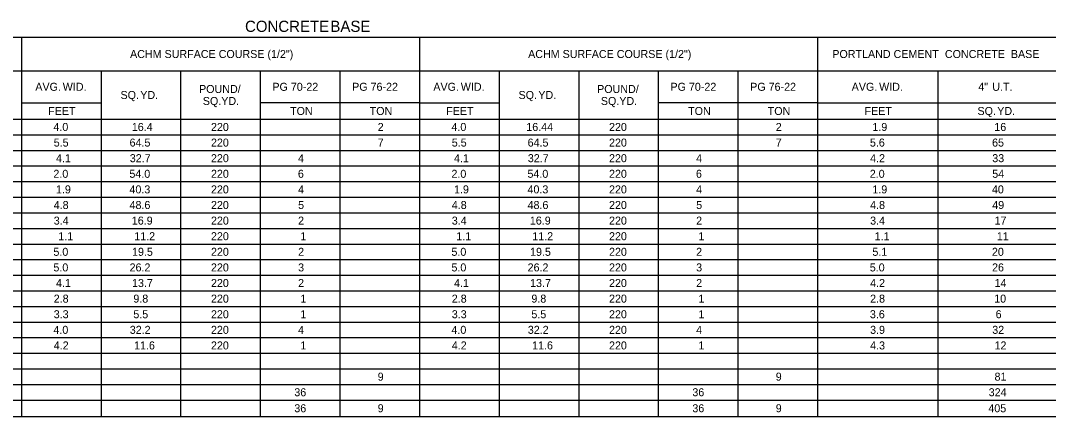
# Model space of a CAD drawing. Extents: x 1226567 to 1228151, y 151309 to 152305.
# Drawn here: x 1227158 to 1227800, y 151364 to 151611 of the extents above; entities that cross this region are included whole.
import ezdxf

# ---------------------------------------------------------------- set-up
doc = ezdxf.new("R2010")
doc.units = 0
doc.layers.add('R_Dimension', color=7, linetype='Continuous')

msp = doc.modelspace()

# ---------------------------------------------------------------- linework, layer by layer
at = {"layer": 'R_Dimension'}
for p, q in [((1226721.38, 151600.64), (1227956.7, 151600.64)), ((1227159.15, 151363.71), (1227159.15, 151600.64)), ((1227407.78, 151363.71), (1227407.78, 151600.64)), ((1227656.4, 151363.71), (1227656.4, 151600.64)), ((1227009.98, 151579.68), (1227956.7, 151579.68)), ((1227208.88, 151363.71), (1227208.88, 151579.68)), ((1227258.6, 151363.71), (1227258.6, 151579.68)), ((1227308.33, 151363.71), (1227308.33, 151579.68)), ((1227308.33, 151559.69), (1227308.33, 151579.68)), ((1227358.05, 151363.71), (1227358.05, 151579.68)), ((1227457.5, 151363.71), (1227457.5, 151579.68)), ((1227507.23, 151363.71), (1227507.23, 151579.68)), ((1227556.95, 151363.71), (1227556.95, 151579.68)), ((1227556.95, 151559.69), (1227556.95, 151579.68)), ((1227606.68, 151363.71), (1227606.68, 151579.68)), ((1227731.48, 151363.71), (1227731.48, 151579.68)), ((1227159.15, 151559.69), (1227208.88, 151559.69)), ((1227407.78, 151559.69), (1227308.33, 151559.69)), ((1227407.78, 151559.69), (1227457.5, 151559.69)), ((1227656.4, 151559.69), (1227556.95, 151559.69)), ((1227656.4, 151559.69), (1227956.7, 151559.69)), ((1226721.38, 151549.45), (1227757.8, 151549.45)), ((1227059.7, 151549.45), (1227208.88, 151549.45)), ((1227208.88, 151549.45), (1227358.05, 151549.45)), ((1227457.5, 151549.45), (1227956.7, 151549.45)), ((1226721.38, 151539.7), (1227956.7, 151539.7)), ((1226721.38, 151529.95), (1227956.7, 151529.95)), ((1226721.38, 151520.2), (1227956.7, 151520.2)), ((1226721.38, 151510.45), (1227956.7, 151510.45)), ((1226721.38, 151500.7), (1227956.7, 151500.7)), ((1226721.38, 151490.95), (1227956.7, 151490.95)), ((1226721.38, 151481.2), (1227956.7, 151481.2)), ((1226721.38, 151471.45), (1227956.7, 151471.45)), ((1226721.38, 151461.7), (1227956.7, 151461.7)), ((1226721.38, 151451.95), (1227956.7, 151451.95)), ((1226721.38, 151442.2), (1227956.7, 151442.2)), ((1226721.38, 151432.45), (1227956.7, 151432.45)), ((1226721.38, 151422.7), (1227956.7, 151422.7)), ((1226721.38, 151412.95), (1227956.7, 151412.95)), ((1226721.38, 151403.2), (1227956.7, 151403.2)), ((1226721.38, 151393.45), (1227956.7, 151393.45)), ((1226721.38, 151383.7), (1227956.7, 151383.7)), ((1226721.38, 151373.95), (1227956.7, 151373.95)), ((1226721.38, 151363.71), (1227956.7, 151363.71))]:
    msp.add_line(p, q, dxfattribs=at)

# ---------------------------------------------------------------- texts
for s, height, p in [('CONCRETE', 7, (1227298.62, 151603.96)), (' BASE', 7, (1227349.33, 151603.96)), ('ACHM SURFACE COURSE (1/2")', 5, (1227226.81, 151587.66)), ('ACHM SURFACE COURSE (1/2")', 5, (1227475.44, 151587.66)), ('PORTLAND', 5, (1227665.44, 151587.66)), (' CEMENT', 5, (1227701.85, 151587.66)), (' CONCRETE', 5, (1227733.9, 151587.66)), (' BASE', 5, (1227775.12, 151587.66)), ('AVG.', 5, (1227167.62, 151567.18)), (' WID.', 5, (1227182.89, 151567.18)), ('POUND/', 5, (1227269.9, 151565.81)), ('PG 70-22', 5, (1227315.71, 151567.18)), ('PG 76-22', 5, (1227365.51, 151567.18)), ('AVG.', 5, (1227416.24, 151567.18)), (' WID.', 5, (1227431.52, 151567.18)), ('POUND/', 5, (1227518.53, 151565.81)), ('PG 70-22', 5, (1227564.34, 151567.18)), ('PG 76-22', 5, (1227614.14, 151567.18)), ('AVG.', 5, (1227677.54, 151567.18)), (' WID.', 5, (1227692.82, 151567.18)), ('4"', 5, (1227756.61, 151567.18)), (' U.T.', 5, (1227763.5, 151567.18)), ('SQ.', 5, (1227220.85, 151562.06)), (' YD.', 5, (1227231.32, 151562.06)), ('SQ.', 5, (1227469.47, 151562.06)), (' YD.', 5, (1227479.95, 151562.06)), ('SQ.YD.', 5, (1227272.25, 151558.31)), ('SQ.YD.', 5, (1227520.87, 151558.31)), ('FEET', 5, (1227175.65, 151552.07)), ('TON', 5, (1227326.75, 151552.07)), ('TON', 5, (1227376.48, 151552.07)), ('FEET', 5, (1227424.28, 151552.07)), ('TON', 5, (1227575.38, 151552.07)), ('TON', 5, (1227625.1, 151552.07)), ('FEET', 5, (1227685.58, 151552.07)), ('SQ.', 5, (1227756.12, 151552.07)), (' YD.', 5, (1227766.6, 151552.07)), ('4.0', 5, (1227178.92, 151542.08)), ('16.4', 5, (1227227.91, 151542.08)), ('220', 5, (1227277.34, 151542.08)), ('2', 5, (1227381.5, 151542.08)), ('4.0', 5, (1227427.54, 151542.08)), ('16.44', 5, (1227474.3, 151542.08)), ('220', 5, (1227525.97, 151542.08)), ('2', 5, (1227630.12, 151542.08)), ('1.9', 5, (1227690.46, 151542.08)), ('16', 5, (1227766.63, 151542.08)), ('5.5', 5, (1227179.13, 151532.33)), ('64.5', 5, (1227226.5, 151532.33)), ('220', 5, (1227277.34, 151532.33)), ('7', 5, (1227381.5, 151532.33)), ('5.5', 5, (1227427.76, 151532.33)), ('64.5', 5, (1227475.12, 151532.33)), ('220', 5, (1227525.97, 151532.33)), ('7', 5, (1227630.12, 151532.33)), ('5.6', 5, (1227688.92, 151532.33)), ('65', 5, (1227765.24, 151532.33)), ('4.1', 5, (1227180.55, 151522.58)), ('32.7', 5, (1227226.62, 151522.58)), ('220', 5, (1227277.34, 151522.58)), ('4', 5, (1227331.77, 151522.58)), ('4.1', 5, (1227429.18, 151522.58)), ('32.7', 5, (1227475.24, 151522.58)), ('220', 5, (1227525.97, 151522.58)), ('4', 5, (1227580.4, 151522.58)), ('4.2', 5, (1227689.06, 151522.58)), ('33', 5, (1227765.35, 151522.58)), ('2.0', 5, (1227178.92, 151512.83)), ('54.0', 5, (1227226.4, 151512.83)), ('220', 5, (1227277.34, 151512.83)), ('6', 5, (1227331.64, 151512.83)), ('2.0', 5, (1227427.54, 151512.83)), ('54.0', 5, (1227475.02, 151512.83)), ('220', 5, (1227525.97, 151512.83)), ('6', 5, (1227580.26, 151512.83)), ('2.0', 5, (1227688.84, 151512.83)), ('54', 5, (1227765.35, 151512.83)), ('1.9', 5, (1227180.53, 151503.08)), ('40.3', 5, (1227226.42, 151503.08)), ('220', 5, (1227277.34, 151503.08)), ('4', 5, (1227331.77, 151503.08)), ('1.9', 5, (1227429.16, 151503.08)), ('40.3', 5, (1227475.04, 151503.08)), ('220', 5, (1227525.97, 151503.08)), ('4', 5, (1227580.4, 151503.08)), ('1.9', 5, (1227690.46, 151503.08)), ('40', 5, (1227765.14, 151503.08)), ('4.8', 5, (1227179.13, 151493.33)), ('48.6', 5, (1227226.48, 151493.33)), ('220', 5, (1227277.34, 151493.33)), ('5', 5, (1227331.77, 151493.33)), ('4.8', 5, (1227427.76, 151493.33)), ('48.6', 5, (1227475.1, 151493.33)), ('220', 5, (1227525.97, 151493.33)), ('5', 5, (1227580.4, 151493.33)), ('4.8', 5, (1227689.06, 151493.33)), ('49', 5, (1227765.34, 151493.33)), ('3.4', 5, (1227179.13, 151483.58)), ('16.9', 5, (1227227.89, 151483.58)), ('220', 5, (1227277.34, 151483.58)), ('2', 5, (1227331.77, 151483.58)), ('3.4', 5, (1227427.76, 151483.58)), ('16.9', 5, (1227476.52, 151483.58)), ('220', 5, (1227525.97, 151483.58)), ('2', 5, (1227580.4, 151483.58)), ('3.4', 5, (1227689.06, 151483.58)), ('17', 5, (1227766.77, 151483.58)), ('1.1', 5, (1227181.97, 151473.83)), ('11.2', 5, (1227229.45, 151473.83)), ('220', 5, (1227277.34, 151473.83)), ('1', 5, (1227333.19, 151473.83)), ('1.1', 5, (1227430.59, 151473.83)), ('11.2', 5, (1227478.07, 151473.83)), ('220', 5, (1227525.97, 151473.83)), ('1', 5, (1227581.82, 151473.83)), ('1.1', 5, (1227691.89, 151473.83)), ('11', 5, (1227768.19, 151473.83)), ('5.0', 5, (1227178.92, 151464.08)), ('19.5', 5, (1227228.03, 151464.08)), ('220', 5, (1227277.34, 151464.08)), ('2', 5, (1227331.77, 151464.08)), ('5.0', 5, (1227427.54, 151464.08)), ('19.5', 5, (1227476.66, 151464.08)), ('220', 5, (1227525.97, 151464.08)), ('2', 5, (1227580.4, 151464.08)), ('5.1', 5, (1227690.48, 151464.08)), ('20', 5, (1227765.14, 151464.08)), ('5.0', 5, (1227178.92, 151454.33)), ('26.2', 5, (1227226.5, 151454.33)), ('220', 5, (1227277.34, 151454.33)), ('3', 5, (1227331.77, 151454.33)), ('5.0', 5, (1227427.54, 151454.33)), ('26.2', 5, (1227475.12, 151454.33)), ('220', 5, (1227525.97, 151454.33)), ('3', 5, (1227580.4, 151454.33)), ('5.0', 5, (1227688.84, 151454.33)), ('26', 5, (1227765.22, 151454.33)), ('4.1', 5, (1227180.55, 151444.58)), ('13.7', 5, (1227228.03, 151444.58)), ('220', 5, (1227277.34, 151444.58)), ('2', 5, (1227331.77, 151444.58)), ('4.1', 5, (1227429.18, 151444.58)), ('13.7', 5, (1227476.66, 151444.58)), ('220', 5, (1227525.97, 151444.58)), ('2', 5, (1227580.4, 151444.58)), ('4.2', 5, (1227689.06, 151444.58)), ('14', 5, (1227766.77, 151444.58)), ('2.8', 5, (1227179.13, 151434.83)), ('9.8', 5, (1227228.86, 151434.83)), ('220', 5, (1227277.34, 151434.83)), ('1', 5, (1227333.19, 151434.83)), ('2.8', 5, (1227427.76, 151434.83)), ('9.8', 5, (1227477.48, 151434.83)), ('220', 5, (1227525.97, 151434.83)), ('1', 5, (1227581.82, 151434.83)), ('2.8', 5, (1227689.06, 151434.83)), ('10', 5, (1227766.56, 151434.83)), ('3.3', 5, (1227179.13, 151425.08)), ('5.5', 5, (1227228.86, 151425.08)), ('220', 5, (1227277.34, 151425.08)), ('1', 5, (1227333.19, 151425.08)), ('3.3', 5, (1227427.76, 151425.08)), ('5.5', 5, (1227477.48, 151425.08)), ('220', 5, (1227525.97, 151425.08)), ('1', 5, (1227581.82, 151425.08)), ('3.6', 5, (1227688.92, 151425.08)), ('6', 5, (1227767.46, 151425.08)), ('4.0', 5, (1227178.92, 151415.33)), ('32.2', 5, (1227226.62, 151415.33)), ('220', 5, (1227277.34, 151415.33)), ('4', 5, (1227331.77, 151415.33)), ('4.0', 5, (1227427.54, 151415.33)), ('32.2', 5, (1227475.24, 151415.33)), ('220', 5, (1227525.97, 151415.33)), ('4', 5, (1227580.4, 151415.33)), ('3.9', 5, (1227689.04, 151415.33)), ('32', 5, (1227765.35, 151415.33)), ('4.2', 5, (1227179.13, 151405.58)), ('11.6', 5, (1227229.31, 151405.58)), ('220', 5, (1227277.34, 151405.58)), ('1', 5, (1227333.19, 151405.58)), ('4.2', 5, (1227427.76, 151405.58)), ('11.6', 5, (1227477.94, 151405.58)), ('220', 5, (1227525.97, 151405.58)), ('1', 5, (1227581.82, 151405.58)), ('4.3', 5, (1227689.06, 151405.58)), ('12', 5, (1227766.77, 151405.58)), ('9', 5, (1227381.48, 151386.08)), ('9', 5, (1227630.1, 151386.08)), ('81', 5, (1227766.77, 151386.08)), ('36', 5, (1227329.39, 151376.33)), ('36', 5, (1227578.02, 151376.33)), ('324', 5, (1227763.11, 151376.33)), ('36', 5, (1227329.39, 151366.33)), ('9', 5, (1227381.48, 151366.33)), ('36', 5, (1227578.02, 151366.33)), ('9', 5, (1227630.1, 151366.33)), ('405', 5, (1227762.91, 151366.33))]:
    msp.add_text(s, height=height, dxfattribs=at).set_placement(p)

doc.saveas('drawing.dxf')
